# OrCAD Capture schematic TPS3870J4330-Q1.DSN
size A; title: TPS3870-Q1 High-Accuracy Overvoltage Supervisor; rev: 1.0; note: SNVSBI5 - JULY 2019
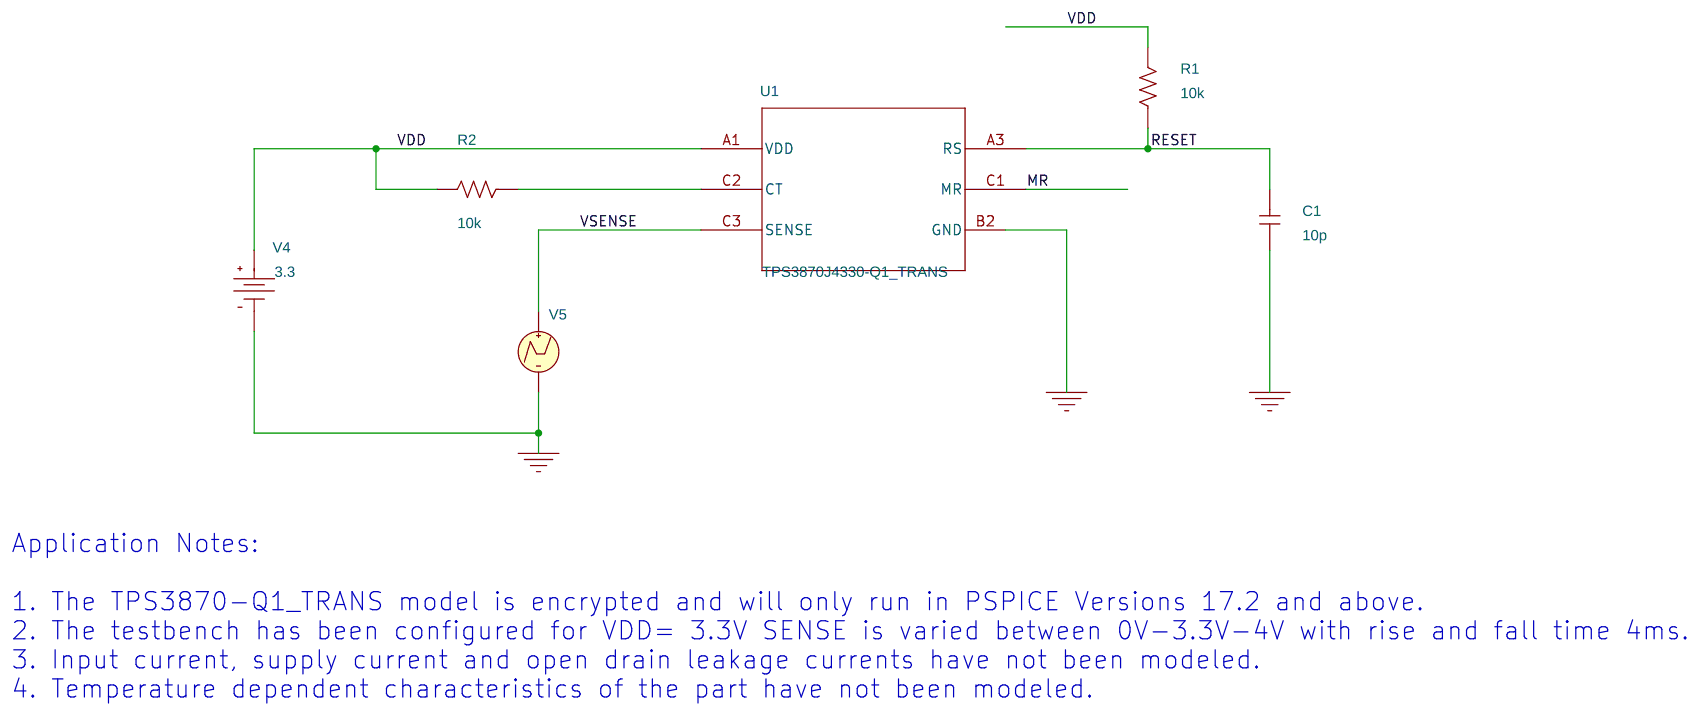
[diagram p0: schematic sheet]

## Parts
C1  10p  [RAD/CK05]
R1  10k  [AX/RC05]
R2  10k  [AX/RC05]
U1  TPS3870J4330-Q1_TRANS  [YKA0005AFAF]
V4  VDC
V5  VPWL

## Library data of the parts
C1 = C
R1 R2 = R
U1 = TPS3703A4330-Q1_TRANS
V4 = VDC: DC: 3.3
V5 = VPWL: PSpiceTemplate: V^@REFDES %+ %- ?DC|DC @DC| ?AC|AC @AC|\n+PWL @T1 @V1 @T2 @V2 #T3/@T3 @V3/ #T4/@T4 @V4/ #T5/@T5 @V5/ #T6/@T6 @V6/ #T7/@T7 @V7/ #T8/@T8 @V8/ #T9/@T9 @V9/ #T10/@T10 @V10/; T1: 0; T2: 12m; T3: 16m; T4: 240m; T5: 244m; T6: 450m; T7: 454m; T8: 662m; T9: 666m; V1: 0; V2: 0; V3: 3.3; V4: 3.3; V5: 4; V6: 4; V7: 3.3; V8: 3.3; V9: 0

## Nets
VDD: R1.2 R2.2 U1.A1(VDD) V4.0(+)
0: C1.1 U1.B2(GND) V4.1(-) V5.2(-)
MR: U1.C1(MR)
RESET: C1.2 R1.1 U1.A3(RS)
VSENSE: U1.C3(SENSE) V5.1(+)
N16776067: R2.1 U1.C2(CT)

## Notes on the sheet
- Application Notes:
  1. The TPS3870-Q1_TRANS model is encrypted and will only run in PSPICE Versions 17.2 and above.
  2. The testbench has been configured for VDD= 3.3V SENSE is varied between 0V-3.3V-4V with rise and fall time 4ms.
  3. Input current, supply current and open drain leakage currents have not been modeled.
  4. Temperature dependent characteristics of the part have not been modeled.
